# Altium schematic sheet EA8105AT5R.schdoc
size 127 x 101 mm
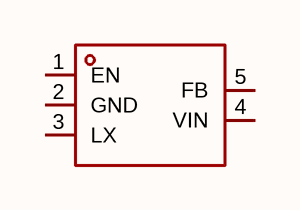
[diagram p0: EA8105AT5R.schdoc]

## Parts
U?  ea8105at5r  [SOT-23-5_L2.9-W1.6-P0.95-LS2.8-BR]  (value not drawn)

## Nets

Not connected (* = marked no-connect by the designer): U? 1(EN) 2(GND) 3(LX) 4(VIN) 5(FB)

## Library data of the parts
U? = ea8105at5r: 功能类型:降压型;工作电压:2.5V~6.5V;输出电压:-;输出电流:2A;输出类型:可调;; Manufacturer: everanalog(申风); AddInBom: yes; ModelId: 7ba65df16e7b4570af156e925f9c37fe; ModelTransform: 114.173,114.173,0,90,0,0,0,0,0; Function: 降压型; Output Current: 2A; Frequency - Switching: 1MHz; Synchronous Rectifier: 是; Number of Outputs: 1; Topology: 降压式; Quiescent Current: 200uA; Switch tube (built-in/external): 内置; Output Type: 可调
